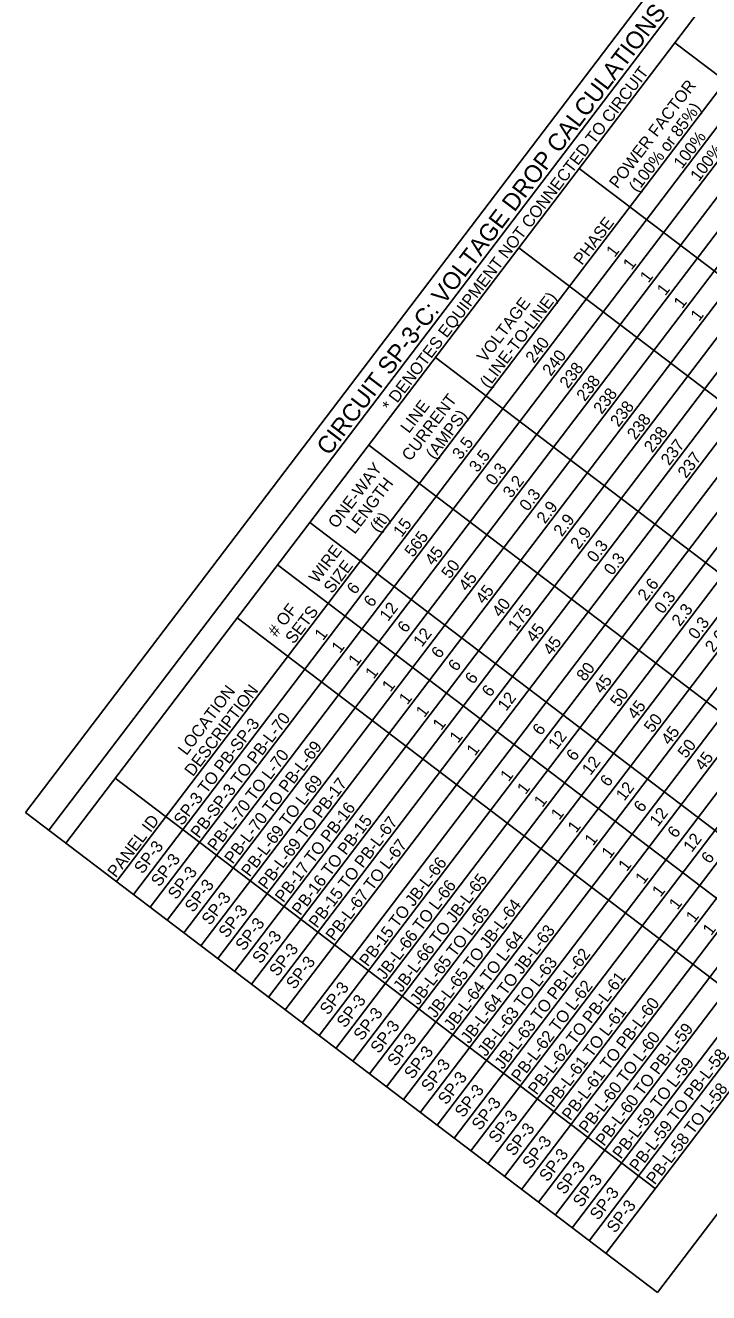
# Model space of a CAD drawing. Extents: x 1289840 to 1300285, y 220865 to 232461.
# Drawn here: x 1298779 to 1299156, y 231266 to 231966 of the extents above; entities that cross this region are included whole.
import ezdxf

# ---------------------------------------------------------------- set-up
doc = ezdxf.new("R2010")
doc.units = 0
doc.layers.add('Default', color=7, linetype='Continuous')
doc.layers.add('R_No Plot', color=7, linetype='Continuous')

msp = doc.modelspace()

# ---------------------------------------------------------------- linework, layer by layer
at = {"layer": 'Default'}
for p, q in [((1298779.43, 231530.95), (1299297.82, 232212.68)), ((1298792.46, 231521.04), (1299310.86, 232202.77)), ((1298801.78, 231513.96), (1299320.17, 232195.68)), ((1298829.72, 231492.71), (1299348.11, 232174.44)), ((1298839.03, 231485.63), (1299357.43, 232167.36)), ((1298848.34, 231478.55), (1299366.74, 232160.28)), ((1298857.66, 231471.46), (1299376.05, 232153.19)), ((1298866.97, 231464.38), (1299385.37, 232146.11)), ((1298876.28, 231457.3), (1299394.68, 232139.03)), ((1298885.6, 231450.22), (1299403.99, 232131.95)), ((1298894.91, 231443.14), (1299413.31, 232124.87)), ((1298904.22, 231436.05), (1299422.62, 232117.78)), ((1298913.54, 231428.97), (1299431.93, 232110.7)), ((1298922.85, 231421.89), (1299441.25, 232103.62)), ((1298932.16, 231414.81), (1299450.56, 232096.54)), ((1298941.48, 231407.73), (1299459.87, 232089.46)), ((1298950.79, 231400.64), (1299469.19, 232082.37)), ((1298960.1, 231393.56), (1299478.5, 232075.29)), ((1298969.42, 231386.48), (1299487.81, 232068.21)), ((1298978.73, 231379.4), (1299497.13, 232061.13)), ((1298988.04, 231372.32), (1299506.44, 232054.05)), ((1298997.36, 231365.24), (1299515.75, 232046.96)), ((1299006.67, 231358.15), (1299525.07, 232039.88)), ((1299015.98, 231351.07), (1299534.38, 232032.8)), ((1299025.3, 231343.99), (1299543.69, 232025.72)), ((1299034.61, 231336.91), (1299553.01, 232018.64)), ((1299043.92, 231329.83), (1299562.32, 232011.55)), ((1299053.24, 231322.74), (1299571.63, 232004.47)), ((1299062.55, 231315.66), (1299580.95, 231997.39)), ((1299071.86, 231308.58), (1299590.26, 231990.31)), ((1299081.18, 231301.5), (1299599.57, 231983.23)), ((1299090.49, 231294.42), (1299608.89, 231976.15)), ((1299099.8, 231287.33), (1299618.2, 231969.06)), ((1299435.84, 231729.25), (1299137.82, 231955.87)), ((1299128.21, 231265.73), (1299646.6, 231947.46)), ((1299383.08, 231659.86), (1299085.05, 231886.49)), ((1299349.79, 231616.09), (1299051.77, 231842.71)), ((1299303.76, 231555.56), (1299005.74, 231782.18)), ((1299266.94, 231507.13), (1298968.91, 231733.75)), ((1299234.36, 231464.29), (1298936.33, 231690.91)), ((1299216.65, 231441), (1298918.63, 231667.62)), ((1299194.35, 231411.67), (1298896.32, 231638.29)), ((1299127.07, 231323.19), (1298829.04, 231549.81)), ((1299128.21, 231265.73), (1298779.43, 231530.95))]:
    msp.add_line(p, q, dxfattribs=at)
at = {"layer": 'R_No Plot'}
msp.add_line((1298779.43, 231530.95), (1298779.43, 231530.95), dxfattribs=at)

# ---------------------------------------------------------------- texts
at = {"layer": 'Default'}
for s, height, p in [('CIRCUIT SP-3-C: VOLTAGE DROP CALCULATIONS', 9.6, (1298947, 231727.44)), ('* DENOTES EQUIPMENT NOT CONNECTED TO CIRCUIT', 6.6, (1298981.05, 231751.89)), ('POWER FACTOR ', 6.6, (1299106.24, 231874.89)), ('(100% or 85%)', 6.6, (1299117.12, 231872.85)), ('100%', 6.6, (1299141.77, 231885.93)), ('100%', 6.6, (1299151.08, 231878.85)), ('PHASE', 6.6, (1299086.56, 231832.65)), ('1', 6.6, (1299104.61, 231837.07)), ('1', 6.6, (1299113.93, 231829.99)), ('1', 6.6, (1299123.24, 231822.91)), ('VOLTAGE ', 6.6, (1299033.26, 231778.92)), ('(LINE-TO-LINE)', 6.6, (1299034.91, 231764.74)), ('1', 6.6, (1299132.55, 231815.82)), ('1', 6.6, (1299141.87, 231808.74)), ('1', 6.6, (1299151.18, 231801.66)), ('240', 6.6, (1299060.06, 231778.48)), ('240', 6.6, (1299069.38, 231771.4)), ('238', 6.6, (1299078.86, 231764.55)), ('238', 6.6, (1299088.18, 231757.47)), ('CURRENT ', 6.6, (1298991.82, 231724.42)), ('238', 6.6, (1299097.49, 231750.38)), ('LINE ', 6.6, (1298991.09, 231739.82)), ('(AMPS)', 6.6, (1299005.06, 231725.48)), ('238', 6.6, (1299106.8, 231743.3)), ('238', 6.6, (1299116.12, 231736.22)), ('3.5', 6.6, (1299019.63, 231725.3)), ('238', 6.6, (1299125.43, 231729.14)), ('3.5', 6.6, (1299028.94, 231718.22)), ('237', 6.6, (1299134.74, 231722.06)), ('ONE-WAY', 6.6, (1298951.14, 231687.28)), ('237', 6.6, (1299144.06, 231714.97)), ('0.3', 6.6, (1299038.1, 231710.93)), ('LENGTH', 6.6, (1298961.19, 231684.14)), ('3.2', 6.6, (1299047.57, 231704.06)), ('0.3', 6.6, (1299056.72, 231696.77)), ('2.9', 6.6, (1299066.18, 231689.87)), ('(ft)', 6.6, (1298974.26, 231684.97)), ('15', 6.6, (1298987.03, 231682.44)), ('2.9', 6.6, (1299075.49, 231682.79)), ('565', 6.6, (1298993.33, 231671.39)), ('2.9', 6.6, (1299084.8, 231675.71)), ('WIRE', 6.6, (1298940.58, 231657.03)), ('45', 6.6, (1299004.53, 231666.79)), ('0.3', 6.6, (1299093.97, 231668.44)), ('SIZE', 6.6, (1298948.71, 231651.37)), ('50', 6.6, (1299013.67, 231659.48)), ('0.3', 6.6, (1299103.29, 231661.36)), ('45', 6.6, (1299023.15, 231652.62)), ('6', 6.6, (1298961.46, 231650.85)), ('45', 6.6, (1299032.47, 231645.54)), ('2.6', 6.6, (1299121.96, 231647.26)), ('6', 6.6, (1298970.78, 231643.77)), ('40', 6.6, (1299041.61, 231638.23)), ('0.3', 6.6, (1299131.23, 231640.11)), ('# OF ', 6.6, (1298918.01, 231627.35)), ('SETS', 6.6, (1298927.51, 231623.49)), ('12', 6.6, (1298979.54, 231635.96)), ('175', 6.6, (1299050.43, 231630.51)), ('2.3', 6.6, (1299140.7, 231633.24)), ('6', 6.6, (1298989.4, 231629.6)), ('45', 6.6, (1299060.41, 231624.3)), ('0.3', 6.6, (1299149.85, 231625.95)), ('1', 6.6, (1298943.68, 231625.43)), ('12', 6.6, (1298998.17, 231621.8)), ('45', 6.6, (1299069.72, 231617.21)), ('2.0', 6.6, (1299159.15, 231618.85)), ('1', 6.6, (1298952.99, 231618.35)), ('6', 6.6, (1299008.03, 231615.44)), ('1', 6.6, (1298962.3, 231611.26)), ('6', 6.6, (1299017.34, 231608.36)), ('80', 6.6, (1299088.17, 231602.82)), ('1', 6.6, (1298971.62, 231604.18)), ('6', 6.6, (1299026.66, 231601.27)), ('45', 6.6, (1299097.66, 231595.97)), ('LOCATION', 6.6, (1298868.31, 231561.99)), ('DESCRIPTION', 6.6, (1298871.88, 231550.33)), ('1', 6.6, (1298980.93, 231597.1)), ('6', 6.6, (1299035.97, 231594.19)), ('50', 6.6, (1299106.8, 231588.66)), ('1', 6.6, (1298990.24, 231590.02)), ('12', 6.6, (1299044.73, 231586.39)), ('45', 6.6, (1299116.29, 231581.81)), ('PB-SP-3 TO PB-L-70', 6.6, (1298875.27, 231516.13)), ('1', 6.6, (1298999.56, 231582.94)), ('50', 6.6, (1299125.43, 231574.5)), ('SP-3 TO PB-SP-3', 6.6, (1298865.95, 231523.21)), ('1', 6.6, (1299008.87, 231575.85)), ('6', 6.6, (1299063.91, 231572.95)), ('45', 6.6, (1299134.91, 231567.64)), ('1', 6.6, (1299018.18, 231568.77)), ('12', 6.6, (1299072.67, 231565.14)), ('50', 6.6, (1299144.05, 231560.33)), ('PB-L-70 TO L-70', 6.6, (1298884.58, 231509.05)), ('PB-L-70 TO PB-L-69', 6.6, (1298893.89, 231501.97)), ('1', 6.6, (1299027.5, 231561.69)), ('6', 6.6, (1299082.53, 231558.78)), ('45', 6.6, (1299153.54, 231553.48)), ('12', 6.6, (1299091.3, 231550.98)), ('PB-L-69 TO L-69', 6.6, (1298903.21, 231494.89)), ('PB-L-69 TO PB-17', 6.6, (1298912.52, 231487.8)), ('1', 6.6, (1299046.12, 231547.53)), ('6', 6.6, (1299101.16, 231544.62)), ('1', 6.6, (1299055.44, 231540.44)), ('12', 6.6, (1299109.92, 231536.81)), ('PB-17 TO PB-16', 6.6, (1298921.83, 231480.72)), ('1', 6.6, (1299064.75, 231533.36)), ('6', 6.6, (1299119.79, 231530.45)), ('PANEL ID', 6.6, (1298829.38, 231494.44)), ('PB-16 TO PB-15', 6.6, (1298931.15, 231473.64)), ('PB-15 TO PB-L-67', 6.6, (1298940.46, 231466.56)), ('1', 6.6, (1299074.06, 231526.28)), ('12', 6.6, (1299128.55, 231522.65)), ('1', 6.6, (1299083.38, 231519.2)), ('6', 6.6, (1299138.41, 231516.29)), ('SP-3', 6.6, (1298844.09, 231496.5)), ('PB-L-67 TO L-67', 6.6, (1298949.77, 231459.48)), ('1', 6.6, (1299092.69, 231512.12)), ('12', 6.6, (1299147.18, 231508.49)), ('SP-3', 6.6, (1298853.4, 231489.41)), ('1', 6.6, (1299102, 231505.03)), ('6', 6.6, (1299157.04, 231502.13)), ('SP-3', 6.6, (1298862.72, 231482.33)), ('PB-15 TO JB-L-66', 6.6, (1298968.4, 231445.31)), ('1', 6.6, (1299111.32, 231497.95)), ('SP-3', 6.6, (1298872.03, 231475.25)), ('JB-L-66 TO L-66', 6.6, (1298977.71, 231438.23)), ('JB-L-66 TO JB-L-65', 6.6, (1298987.03, 231431.15)), ('1', 6.6, (1299120.63, 231490.87)), ('SP-3', 6.6, (1298881.34, 231468.17)), ('1', 6.6, (1299129.94, 231483.79)), ('SP-3', 6.6, (1298890.66, 231461.09)), ('JB-L-65 TO L-65', 6.6, (1298996.34, 231424.07)), ('JB-L-65 TO JB-L-64', 6.6, (1299005.65, 231416.99)), ('1', 6.6, (1299139.26, 231476.71)), ('SP-3', 6.6, (1298899.97, 231454)), ('1', 6.6, (1299148.57, 231469.62)), ('SP-3', 6.6, (1298909.28, 231446.92)), ('JB-L-64 TO JB-L-63', 6.6, (1299024.28, 231402.82)), ('1', 6.6, (1299157.88, 231462.54)), ('SP-3', 6.6, (1298918.6, 231439.84)), ('JB-L-64 TO L-64', 6.6, (1299014.97, 231409.9)), ('SP-3', 6.6, (1298927.91, 231432.76)), ('JB-L-63 TO PB-L-62', 6.6, (1299042.91, 231388.66)), ('JB-L-63 TO L-63', 6.6, (1299033.59, 231395.74)), ('PB-L-62 TO L-62', 6.6, (1299052.22, 231381.58)), ('PB-L-62 TO PB-L-61', 6.6, (1299061.53, 231374.49)), ('SP-3', 6.6, (1298946.54, 231418.59)), ('SP-3', 6.6, (1298955.85, 231411.51)), ('PB-L-61 TO L-61', 6.6, (1299070.85, 231367.41)), ('PB-L-61 TO PB-L-60', 6.6, (1299080.16, 231360.33)), ('SP-3', 6.6, (1298965.16, 231404.43)), ('SP-3', 6.6, (1298974.48, 231397.35)), ('PB-L-60 TO L-60', 6.6, (1299089.47, 231353.25)), ('PB-L-60 TO PB-L-59', 6.6, (1299098.78, 231346.17)), ('SP-3', 6.6, (1298983.79, 231390.27)), ('SP-3', 6.6, (1298993.1, 231383.18)), ('PB-L-59 TO L-59', 6.6, (1299108.1, 231339.08)), ('PB-L-59 TO PB-L-58', 6.6, (1299117.41, 231332)), ('SP-3', 6.6, (1299002.42, 231376.1)), ('SP-3', 6.6, (1299011.73, 231369.02)), ('PB-L-58 TO L-58', 6.6, (1299126.72, 231324.92)), ('SP-3', 6.6, (1299021.04, 231361.94)), ('SP-3', 6.6, (1299030.36, 231354.86)), ('SP-3', 6.6, (1299039.67, 231347.77)), ('SP-3', 6.6, (1299048.98, 231340.69)), ('SP-3', 6.6, (1299058.3, 231333.61)), ('SP-3', 6.6, (1299067.61, 231326.53)), ('SP-3', 6.6, (1299076.92, 231319.45)), ('SP-3', 6.6, (1299086.24, 231312.37)), ('SP-3', 6.6, (1299095.55, 231305.28)), ('SP-3', 6.6, (1299104.86, 231298.2))]:
    msp.add_text(s, height=height, rotation=52.75013, dxfattribs=at).set_placement(p)

doc.saveas('drawing.dxf')
